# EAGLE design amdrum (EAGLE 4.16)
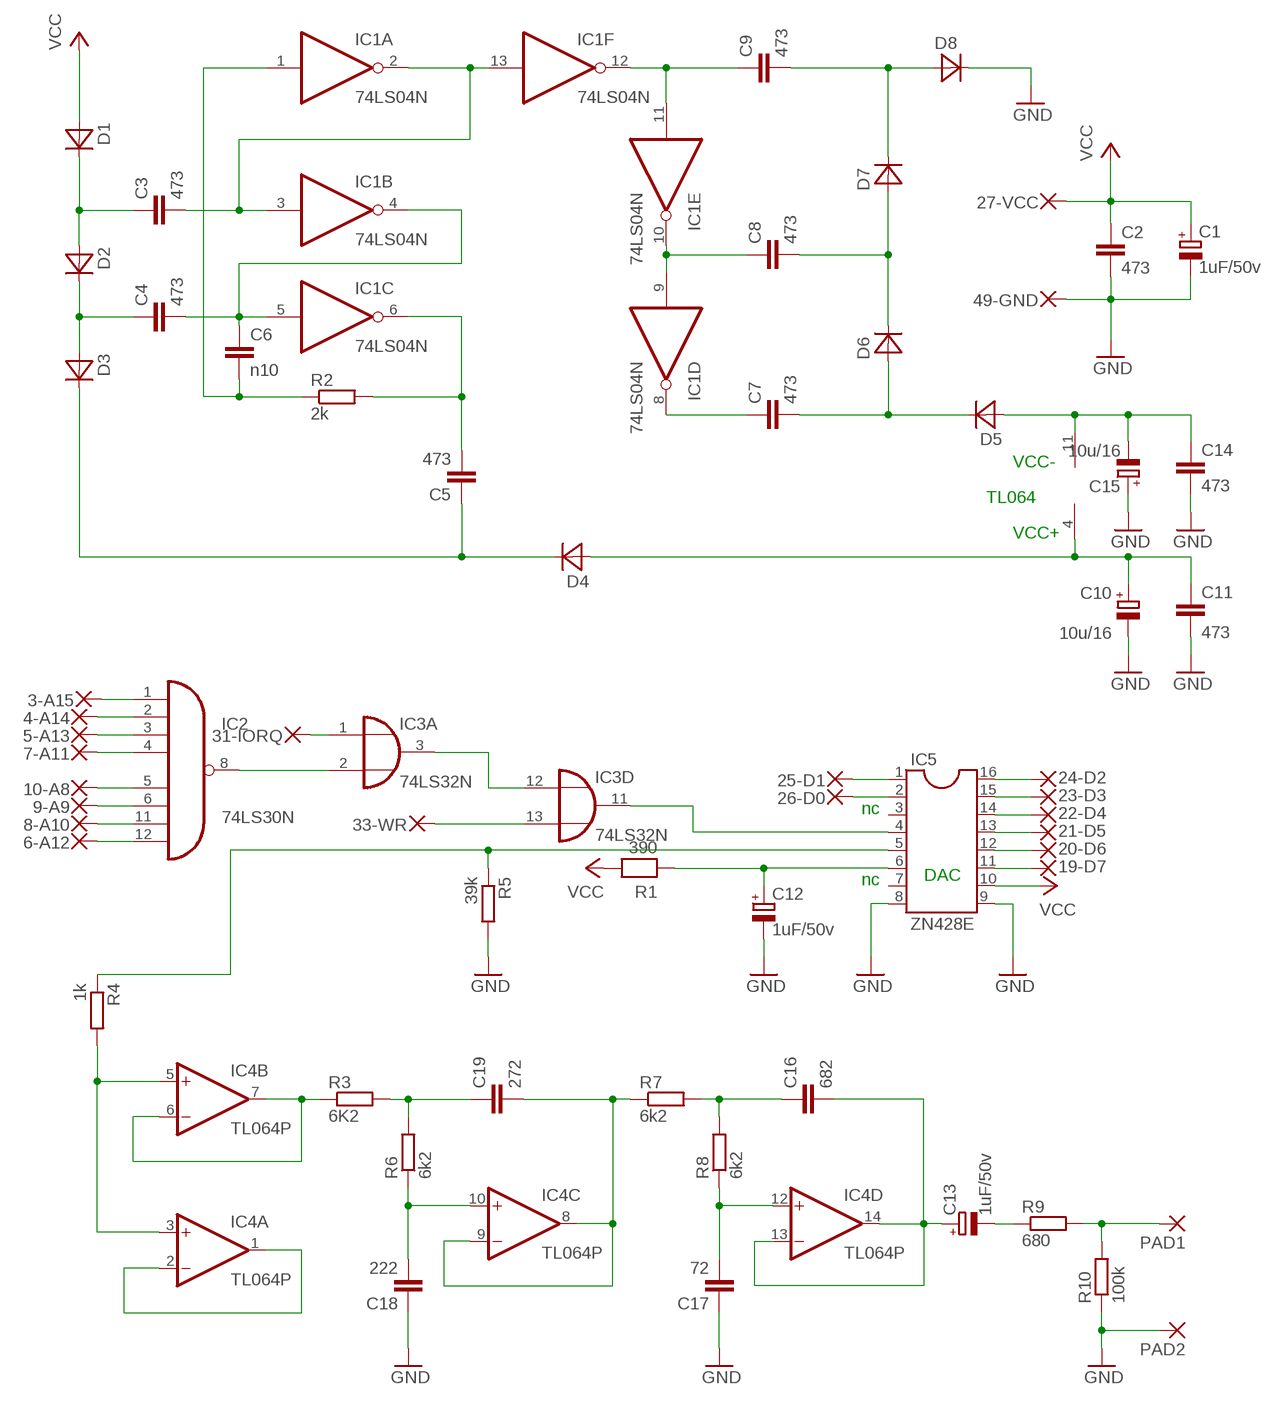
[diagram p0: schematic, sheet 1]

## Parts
3-A15  1,27-REDONDO0.8  [1,27/0,8-REDONDO]
4-A14  1,27-REDONDO0.8  [1,27/0,8-REDONDO]
5-A13  1,27-REDONDO0.8  [1,27/0,8-REDONDO]
6-A12  1,27-REDONDO0.8  [1,27/0,8-REDONDO]
7-A11  1,27-REDONDO0.8  [1,27/0,8-REDONDO]
8-A10  1,27-REDONDO0.8  [1,27/0,8-REDONDO]
9-A9  1,27-REDONDO0.8  [1,27/0,8-REDONDO]
10-A8  1,27-REDONDO0.8  [1,27/0,8-REDONDO]
19-D7  1,27-REDONDO0.8  [1,27/0,8-REDONDO]
20-D6  1,27-REDONDO0.8  [1,27/0,8-REDONDO]
21-D5  1,27-REDONDO0.8  [1,27/0,8-REDONDO]
22-D4  1,27-REDONDO0.8  [1,27/0,8-REDONDO]
23-D3  1,27-REDONDO0.8  [1,27/0,8-REDONDO]
24-D2  1,27-REDONDO0.8  [1,27/0,8-REDONDO]
25-D1  1,27-REDONDO0.8  [1,27/0,8-REDONDO]
26-D0  1,27-REDONDO0.8  [1,27/0,8-REDONDO]
27-VCC  1,27-REDONDO0.8  [1,27/0,8-REDONDO]
31-IORQ  1,27-REDONDO0.8  [1,27/0,8-REDONDO]
33-WR  1,27-REDONDO0.8  [1,27/0,8-REDONDO]
49-GND  1,27-REDONDO0.8  [1,27/0,8-REDONDO]
C1  1uF/50v  CPOL-EUE5-5  [E5-5]
C2  473  C-EU025-025X050  [C025-025X050]
C3  473  C-EU050-024X044  [C050-024X044]
C4  473  C-EU050-024X044  [C050-024X044]
C5  473  C-EU050-024X044  [C050-024X044]
C6  n10  C-EU050-024X044  [C050-024X044]
C7  473  C-EU050-024X044  [C050-024X044]
C8  473  C-EU050-024X044  [C050-024X044]
C9  473  C-EU050-024X044  [C050-024X044]
C10  10u/16  CPOL-EUE5-4  [E5-4]
C11  473  C-EU102-043X133  [C102-043X133]
C12  1uF/50v  CPOL-EUE5-5  [E5-5]
C13  1uF/50v  CPOL-EUE5-5  [E5-5]
C14  473  C-EU025-025X050  [C025-025X050]
C15  10u/16  CPOL-EUE5-4  [E5-4]
C16  682  C-EU025-025X050  [C025-025X050]
C17  72  C-EU050-024X044  [C050-024X044]
C18  222  C-EU050-024X044  [C050-024X044]
C19  272  C-EU050-024X044  [C050-024X044]
D1  DIODE-12,5/2  [D-12,5/2]
D2  DIODE-12,5/2  [D-12,5/2]
D3  DIODE-12,5/2  [D-12,5/2]
D4  DIODE-12,5/2  [D-12,5/2]
D5  DIODE-12,5/2  [D-12,5/2]
D6  DIODE-12,5/2  [D-12,5/2]
D7  DIODE-12,5/2  [D-12,5/2]
D8  DIODE-12,5/2  [D-12,5/2]
IC1  74LS04N  [DIL14]
IC2  74LS30N  [DIL14]
IC3  74LS32N  [DIL14]
IC4  TL064P  [DIL14]
IC5  ZN428E  DIL16  [DIL16]
PAD1  1,6/0,8  [1,6/0,8]
PAD2  1,6/0,8  [1,6/0,8]
R1  390  RESEU-18  [R-18]
R2  2k  R-EU_0207/12  [0207/12]
R3  6K2  R-EU_0207/10  [0207/10]
R4  1k  R-EU_0207/12  [0207/12]
R5  39k  R-EU_0207/12  [0207/12]
R6  6k2  R-EU_0207/12  [0207/12]
R7  6k2  R-EU_0207/12  [0207/12]
R8  6k2  R-EU_0207/10  [0207/10]
R9  680  R-EU_0207/12  [0207/12]
R10  100k  R-EU_0207/12  [0207/12]

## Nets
GND: 49-GND.1(P) C1.- C2.2 C10.- C11.1 C12.- C14.2 C15.+ C17.2 C18.1 D8.P$2(K) IC5.8 IC5.9 PAD2.1(P) R5.2 R10.1
N$25: 3-A15.1(P) IC2.1(I0)
N$26: 4-A14.1(P) IC2.2(I1)
N$27: 6-A12.1(P) IC2.12(I7)
N$28: 5-A13.1(P) IC2.3(I2)
N$30: 7-A11.1(P) IC2.4(I3)
N$31: 8-A10.1(P) IC2.11(I6)
N$32: 10-A8.1(P) IC2.5(I4)
N$33: 9-A9.1(P) IC2.6(I5)
N$34: IC2.8(O) IC3.2(A:I1)
N$35: 31-IORQ.1(P) IC3.1(A:I0)
N$36: 33-WR.1(P) IC3.13(D:I1)
N$37: IC3.3(A:O) IC3.12(D:I0)
N$38: IC3.11(D:O) IC5.4
N$39: 26-D0.1(P) IC5.2
N$40: 25-D1.1(P) IC5.1
N$41: 24-D2.1(P) IC5.16
N$43: 23-D3.1(P) IC5.15
N$47: 22-D4.1(P) IC5.14
N$48: 21-D5.1(P) IC5.13
N$49: 20-D6.1(P) IC5.12
N$54: 19-D7.1(P) IC5.11
N$63: C5.2 IC1.6(C:O) R2.2
N$64: C3.1 D1.P$2(K) D2.P$1(A)
N$65: C3.2 IC1.2(A:O) IC1.3(B:I) IC1.13(F:I)
N$66: C4.1 D2.P$2(K) D3.P$1(A)
N$67: C4.2 C6.1 IC1.4(B:O) IC1.5(C:I)
N$68: C5.1 D3.P$2(K) D4.P$2(K)
N$69: C6.2 IC1.1(A:I) R2.1
N$70: C9.1 IC1.11(E:I) IC1.12(F:O)
N$71: C8.1 IC1.9(D:I) IC1.10(E:O)
N$72: C7.1 IC1.8(D:O)
N$73: C7.2 D5.P$2(K) D6.P$1(A)
N$74: C8.2 D6.P$2(K) D7.P$1(A)
N$75: IC4.6(B:-IN) IC4.7(B:OUT) R3.1
N$76: C9.2 D7.P$2(K) D8.P$1(A)
N$77: C10.+ C11.2 D4.P$1(A) IC4.4(P:V+)
N$78: IC4.1(A:OUT) IC4.2(A:-IN)
N$79: C12.+ IC5.6 R1.1
N$80: IC4.3(A:+IN) IC4.5(B:+IN) R4.2
N$81: C14.1 C15.- D5.P$1(A) IC4.11(P:V-)
N$82: IC5.5 R4.1 R5.1
N$83: C13.- R9.1
N$84: C13.+ C16.2 IC4.13(D:-IN) IC4.14(D:OUT)
N$85: PAD1.1(P) R9.2 R10.2
N$86: C17.1 IC4.12(D:+IN) R8.1
N$87: C16.1 R7.2 R8.2
N$88: C19.1 R3.2 R6.2
N$89: C19.2 IC4.8(C:OUT) IC4.9(C:-IN) R7.1
N$90: C18.2 IC4.10(C:+IN) R6.1
VCC: 27-VCC.1(P) C1.+ C2.1 D1.P$1(A) IC5.10 R1.2
Unconnected: IC3.4(B:I0) IC3.5(B:I1) IC3.6(B:O) IC3.8(C:O) IC3.9(C:I0) IC3.10(C:I1) IC5.3 IC5.7

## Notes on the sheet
- VCC-
- TL064
- VCC+
- nc
- nc | DAC

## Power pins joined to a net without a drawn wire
GND: IC1.7(P:GND) IC2.7(GND) IC3.7(P:GND)
VCC: IC1.14(P:VCC) IC2.14(VCC) IC3.14(P:VCC)

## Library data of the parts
3-A15 4-A14 5-A13 6-A12 7-A11 8-A10 9-A9 10-A8 19-D7 20-D6 21-D5 22-D4 23-D3 24-D2 25-D1 26-D0 27-VCC 31-IORQ 33-WR 49-GND = wirepad2:1,27-REDONDO
C1 C10 C12 C13 C15 = rcl:CPOL-EU: POLARIZED CAPACITOR, European symbol
C2-C9 C11 C14 C16-C19 = rcl:C-EU: CAPACITOR, European symbol
D1-D8 = discrete2:DIODE-12,5/2
IC1 = 74xx-eu:74*04: Hex INVERTER
IC2 = 74xx-eu:74*30: 8-input NAND gate
IC3 = 74xx-eu:74*32: Quad 2-input OR gate
IC4 = linear:TL064: OP AMP
IC5 = ic-package:DIL16: Dual In Line
PAD1 PAD2 = wirepad:1,6/0,8: THROUGH-HOLE PAD
R1 = discrete2:RESEU-18
R2-R10 = rcl:R-EU_: RESISTOR, European symbol

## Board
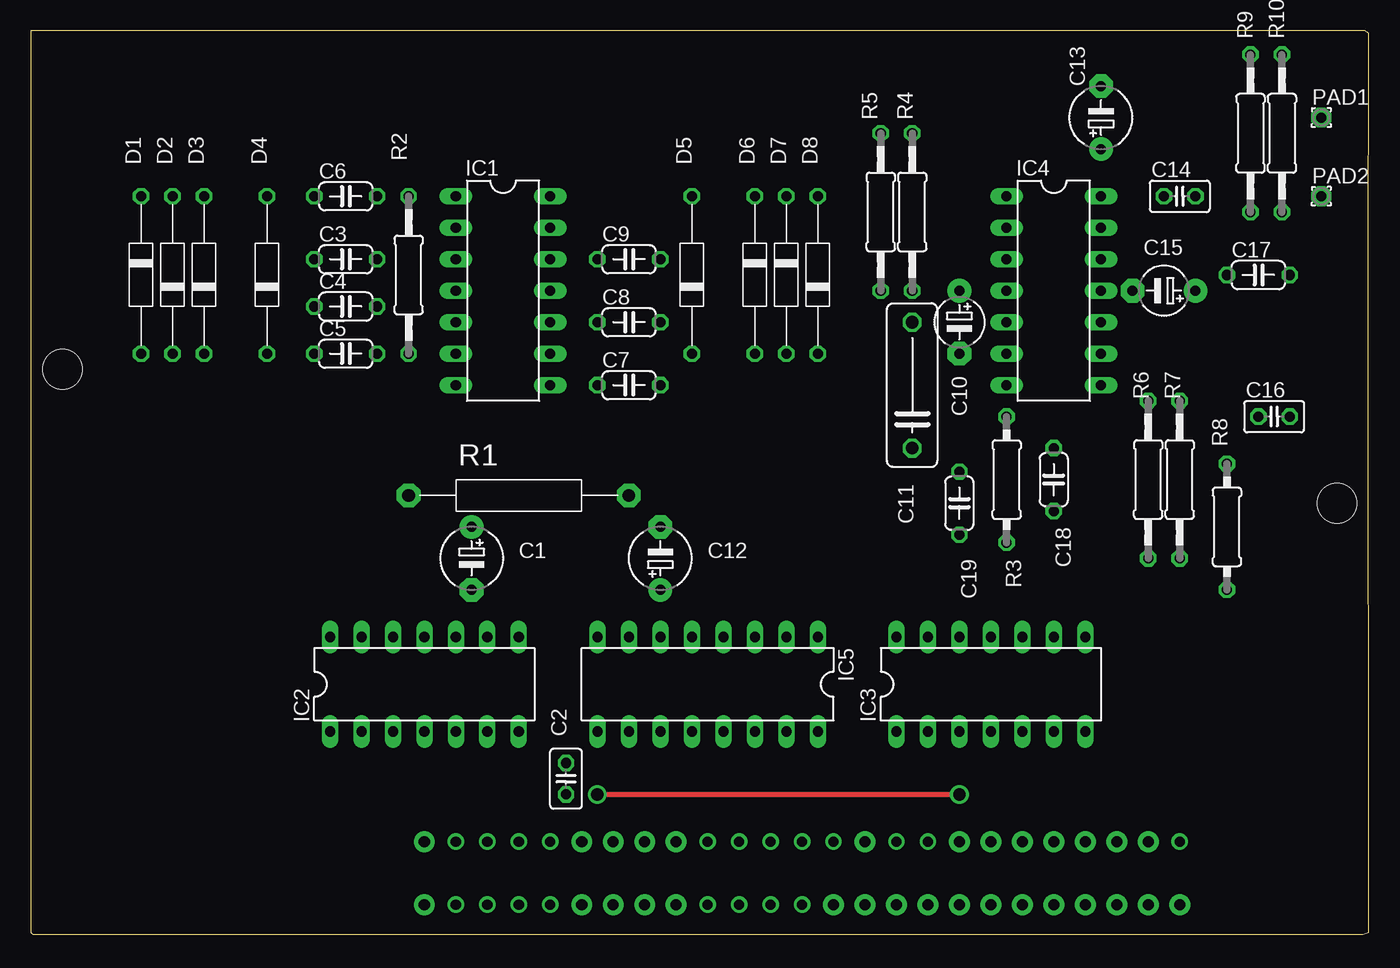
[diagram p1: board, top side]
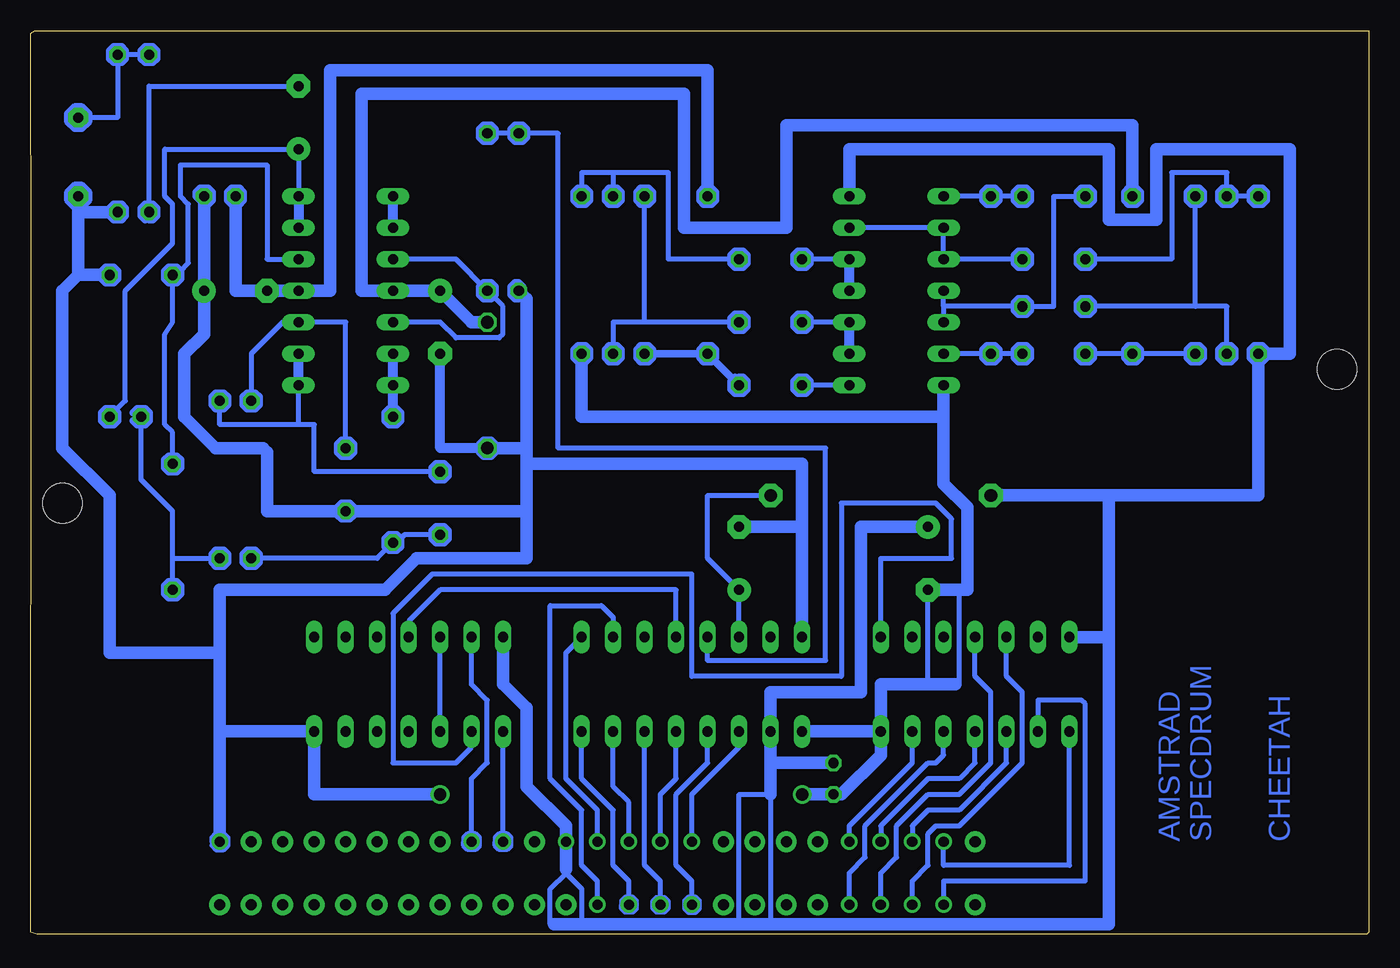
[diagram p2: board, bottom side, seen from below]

Size 107.95 x 72.86 mm. Coordinates in mm from the lower left corner, seen from the top.
Outline: 107.48,0 107.95,0.15 107.94,53.01 107.95,72.69 107.63,72.86 0,72.86 0,0.15 0.15,0 107.48,0
Copper layers (1*16): Top 0.035mm / dielectric 1.5mm / Bottom 0.035mm
Design rules "default": minimum track width 10mil, minimum drill 24mil, track to track 8mil, track to pad 8mil, pad to pad 8mil, via to via 8mil, smd to smd 8mil, copper to edge 40mil, drill to drill 8mil, minimum pad ring 10mil, minimum via ring 8mil, stop-mask expansion 4mil, vias tented up to drill 0mil, thermal gap 10mil
Holes 3.2 mm at 2.54,45.55 105.41,34.76

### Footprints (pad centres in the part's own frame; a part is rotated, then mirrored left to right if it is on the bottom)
1,27/0,8-REDONDO = drill 0.813 pad 1.27 round: 1 0,0
E5-5 = drill 0.813 pad 1.905 round: + -2.54,0 | drill 0.813 pad 1.905 octagon: - 2.54,0
C025-025X050 = drill 0.813 octagon: 1 -1.27,0; 2 1.27,0
C050-024X044 = drill 0.813 octagon: 1 -2.54,0; 2 2.54,0
E5-4 = drill 0.813 pad 1.905 round: + -2.54,0 | drill 0.813 pad 1.905 octagon: - 2.54,0
C102-043X133 = drill 1.016 octagon: 1 -5.08,0; 2 5.08,0
D-12,5/2 = drill 0.813 octagon: P$1 -6.35,0; P$2 6.35,0
DIL14 = drill 0.813 long: 1 -7.62,-3.81; 2 -5.08,-3.81; 3 -2.54,-3.81; 4 0,-3.81; 5 2.54,-3.81; 6 5.08,-3.81; 7 7.62,-3.81; 8 7.62,3.81; 9 5.08,3.81; 10 2.54,3.81; 11 0,3.81; 12 -2.54,3.81; 13 -5.08,3.81; 14 -7.62,3.81
DIL16 = drill 0.813 long: 1 -8.89,-3.81; 2 -6.35,-3.81; 3 -3.81,-3.81; 4 -1.27,-3.81; 5 1.27,-3.81; 6 3.81,-3.81; 7 6.35,-3.81; 8 8.89,-3.81; 9 8.89,3.81; 10 6.35,3.81; 11 3.81,3.81; 12 1.27,3.81; 13 -1.27,3.81; 14 -3.81,3.81; 15 -6.35,3.81; 16 -8.89,3.81
1,6/0,8 = drill 0.813 pad 1.6 octagon: 1 0,0
R-18 = drill 1.016 pad 1.905 octagon: 1 -8.89,0; 2 8.89,0
0207/12 = drill 0.813 octagon: 1 -6.35,0; 2 6.35,0
0207/10 = drill 0.813 octagon: 1 -5.08,0; 2 5.08,0

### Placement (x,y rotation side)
3-A15  34.29,7.46 0 top
4-A14  34.29,2.38 180 top
5-A13  36.83,7.46 0 top
6-A12  36.83,2.38 180 top
7-A11  39.37,7.46 0 top
8-A10  39.37,2.38 180 top
9-A9  41.91,7.46 0 top
10-A8  41.91,2.38 180 top
19-D7  54.61,7.46 0 top
20-D6  54.61,2.38 180 top
21-D5  57.15,7.46 0 top
22-D4  57.15,2.38 180 top
23-D3  59.69,7.46 0 top
24-D2  59.69,2.38 180 top
25-D1  62.23,7.46 0 top
26-D0  62.23,2.38 180 top
27-VCC  64.77,7.46 0 top
31-IORQ  69.85,7.46 0 top
33-WR  72.39,7.46 0 top
49-GND  92.71,7.46 0 top
C1  35.56,30.32 270 top
C2  43.18,12.54 270 top
C3  25.4,54.45 0 top
C4  25.4,50.63 0 top
C5  25.4,46.83 0 top
C6  25.4,59.52 0 top
C7  48.26,44.29 0 top
C8  48.26,49.37 0 top
C9  48.26,54.45 0 top
C10  74.93,49.37 270 top
C11  71.12,44.29 90 top
C12  50.8,30.32 90 top
C13  86.36,65.88 90 top
C14  92.71,59.52 0 top
C15  91.44,51.91 180 top
C16  100.33,41.74 0 top
C17  99.06,53.18 0 top
C18  82.55,36.66 90 top
C19  74.93,34.76 90 top
D1  8.89,53.18 90 top
D2  11.43,53.18 270 top
D3  13.97,53.18 270 top
D4  19.05,53.18 270 top
D5  53.34,53.18 270 top
D6  58.42,53.18 90 top
D7  60.96,53.18 90 top
D8  63.5,53.18 270 top
IC1  38.1,51.91 270 top
IC2  31.75,20.16 0 top
IC3  77.47,20.16 0 top
IC4  82.55,51.91 270 top
IC5  54.61,20.16 180 top
PAD1  104.14,65.88 0 top
PAD2  104.14,59.52 0 top
R1  39.37,35.4 180 top
R2  30.48,53.18 270 top
R3  78.74,36.66 270 top
R4  71.12,58.26 270 top
R5  68.58,58.26 270 top
R6  90.17,36.66 270 top
R7  92.71,36.66 270 top
R8  96.52,32.86 270 top
R9  98.42,64.6 90 top
R10  100.97,64.6 90 top

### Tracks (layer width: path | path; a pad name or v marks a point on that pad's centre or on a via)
GND  (via drill 1, 1 pad 1.42)
  Top 0.406: v45.72,11.27 v74.93,11.27
  Bottom 0.406: 33.34,20.16 33.02,20.16 33.02,27.78 | 35.56,20.16 C1.- | 49-GND.1 93.34,7.46 | 93.34,7.46 93.34,7.14 93.03,6.82 92.39,6.82 92.08,7.14 92.08,7.77 92.39,8.09 93.03,8.09 93.34,7.77 93.34,7.46 | PAD2.1 104.14,60.48 | 104.14,60.48 104.46,60.48 105.09,59.84 105.09,59.21 104.46,58.57 103.82,58.57 103.19,59.21 103.19,59.84 103.82,60.48 104.14,60.48
  Bottom 0.61: C18.1 82.55,34.76 | 82.55,34.76 82.87,34.76 83.19,34.44 83.19,33.81 82.87,33.49 82.23,33.49 81.92,33.81 81.92,34.44 82.23,34.76 82.55,34.76 | C17.2 101.6,53.81 | 101.6,53.81 101.28,53.81 100.97,53.49 100.97,52.86 101.28,52.54 101.92,52.54 102.23,52.86 102.23,53.49 101.92,53.81 101.6,53.81 | R10.1 100.97,58.89 | 100.97,58.89 100.65,58.89 100.33,58.57 100.33,57.94 100.65,57.62 101.28,57.62 101.6,57.94 101.6,58.57 101.28,58.89 100.97,58.89 | D8.P$2 63.5,47.46 | 63.5,47.46 63.82,47.46 64.14,47.14 64.14,46.51 63.82,46.19 63.18,46.19 62.87,46.51 62.87,47.14 63.18,47.46 63.5,47.46 | 71.12,39.84 C11.1 71.12,38.57 | R5.2 69.22,52.22 | 69.22,52.22 68.9,52.54 68.58,52.54 68.26,52.22 68.26,51.59 68.58,51.27 68.9,51.27 69.22,51.59 69.22,52.22 | C14.2 94.61,59.84 | 94.61,59.84 94.3,60.16 93.66,60.16 93.34,59.84 93.34,59.21 93.66,58.89 93.98,58.89 94.61,59.52 94.61,59.84 | 71.12,38.57 71.44,38.57 71.75,38.89 71.75,39.52 71.44,39.84 70.8,39.84 70.48,39.52 70.48,38.89 70.8,38.57 71.12,38.57
  Bottom 0.813: C10.- 74.93,39.2 C11.1
  Bottom 1.016: 92.71,16.35 49-GND.1 | 92.71,16.35 IC3.7 85.09,11.27 v74.93,11.27 | v45.72,11.27 C2.2 42.55,11.27 39.37,14.44 IC2.7 | IC2.7 IC5.9 | IC2.7 39.37,20.16 35.56,20.16 33.34,20.16 | 34.29,41.74 34.29,36.35 32.38,34.44 32.38,27.78 C1.- | 34.29,41.74 IC1.7 | D8.P$2 63.5,41.74 34.29,41.74 | 92.71,16.35 92.71,22.7 | 92.71,22.7 92.71,27.78 79.38,27.78 76.83,30.32 67.94,30.32 67.94,34.12 | 67.94,34.12 67.94,37.94 | 67.94,37.94 67.94,39.2 | 67.94,39.2 C11.1 | 45.72,32.86 45.72,37.94 67.94,37.94 | 45.72,32.86 IC5.8 | 45.72,32.86 C12.- | R5.2 68.26,51.59 67.94,51.27 67.94,39.2 | 104.14,58.26 R10.1 | 104.14,58.26 PAD2.1 | 104.14,53.18 C17.2 | 104.14,53.18 104.14,58.26 | 104.14,53.18 105.41,51.91 105.41,39.2 101.6,35.4 101.6,22.7 92.71,22.7 | C14.2 93.98,58.89 C15.+ 93.98,48.41 95.57,46.83 95.57,41.74 93.03,39.2 89.22,39.2 88.9,38.89 88.9,34.12 C18.1 67.94,34.12
N$2  (via drill 0.9 pad 1.68)
  other vias: 31.75,7.46
N$4  (via drill 0.9 pad 1.68)
  other vias: 72.39,2.38
N$5  (via drill 0.9 pad 1.68)
  other vias: 85.09,7.46
N$8  (via drill 0.9 pad 1.68)
  other vias: 74.93,7.46
N$9  (via drill 0.9 pad 1.68)
  other vias: 77.47,2.38
N$10  (via drill 0.9 pad 1.68)
  other vias: 77.47,7.46
N$11  (via drill 0.9 pad 1.68)
  other vias: 80.01,7.46
N$12  (via drill 0.9 pad 1.68)
  other vias: 82.55,2.38
N$13  (via drill 0.9 pad 1.68)
  other vias: 85.09,2.38
N$14  (via drill 0.9 pad 1.68)
  other vias: 87.63,2.38
N$22  (via drill 0.9 pad 1.68)
  other vias: 90.17,2.38
N$23  (via drill 0.9 pad 1.68)
  other vias: 90.17,7.46
N$24  (via drill 0.9 pad 1.68)
  other vias: 31.75,2.38
N$25
  Bottom 0.406: 3-A15.1 34.29,5.55 24.13,5.55 IC2.1
N$26
  Bottom 0.406: 4-A14.1 34.29,4.28 22.86,4.28 22.86,18.57 23.18,18.89 26.67,18.89 IC2.2
N$27
  Bottom 0.406: IC2.12 29.21,20.79 27.94,19.52 27.94,13.81 33.02,8.73 34.92,8.73 35.56,8.09 35.56,5.55 36.83,4.28 6-A12.1
N$28
  Bottom 0.406: 5-A13.1 36.83,8.73 35.56,10 33.02,10 29.21,13.81 IC2.3
N$29  (via drill 0.9 pad 1.68)
  other vias: 92.71,2.38
N$30
  Bottom 0.406: 7-A11.1 39.37,8.73 35.56,12.54 33.02,12.54 31.75,13.81 IC2.4
N$31
  Bottom 0.406: 8-A10.1 39.37,4.92 38.1,6.18 38.1,8.73 35.56,11.27 33.02,11.27 30.48,13.81 30.48,19.52 31.75,20.79 IC2.11
N$32
  Bottom 0.406: IC2.5 34.29,14.44 34.92,13.81 35.56,13.81 40.64,8.73 40.64,6.18 41.91,4.92 10-A8.1
N$33
  Bottom 0.406: IC2.6 36.83,13.81 41.91,8.73 9-A9.1
N$34
  Bottom 0.406: IC2.8 39.37,30.32 33.66,30.32 33.66,33.49 34.92,34.76 42.55,34.76 42.55,20.79 54.61,20.79 54.61,29.05 75.56,29.05 78.74,25.87 78.74,13.81 73.66,13.81 72.39,15.08 IC3.2
N$35
  Bottom 0.406: IC3.1 31-IORQ.1 70.48,7.46 | 70.48,7.46 70.48,7.14 70.17,6.82 69.53,6.82 69.22,7.14 69.22,7.77 69.53,8.09 70.17,8.09 70.48,7.77 70.48,7.46
N$36
  Bottom 0.406: IC3.13 72.39,20.16 71.12,18.89 71.12,13.81 72.39,12.54 33-WR.1 73.03,7.46 | 73.03,7.46 73.03,7.14 72.71,6.82 72.07,6.82 71.75,7.14 71.75,7.77 72.07,8.09 72.71,8.09 73.03,7.77 73.03,7.46
N$37
  Bottom 0.406: IC3.3 IC3.12
N$38
  Bottom 0.406: IC3.11 77.47,25.23 74.93,27.78 55.88,27.78 IC5.4
N$39
  Bottom 0.406: 26-D0.1 62.23,4.28 63.5,5.55 63.5,10 66.04,12.54 66.04,26.51 61.91,26.51 60.96,25.55 IC5.2
N$40
  Bottom 0.406: 25-D1.1 62.23,10 64.77,12.54 64.77,22.7 IC5.1
N$41
  Bottom 0.305: 60.33,2.38 24-D2.1 | 60.33,2.38 60.33,2.06 60.01,1.74 59.37,1.74 59.05,2.06 59.05,2.69 59.37,3.01 60.01,3.01 60.33,2.69 60.33,2.38
  Bottom 0.406: 24-D2.1 59.69,4.28 60.96,5.55 60.96,10 63.5,12.54 IC5.16
N$42  (via drill 0.9 pad 1.68)
  other vias: 80.01,2.38
N$43
  Bottom 0.406: 23-D3.1 59.69,10.63 60.96,11.9 IC5.15
N$44  (via drill 0.9 pad 1.68)
  other vias: 74.93,2.38
N$45  (via drill 0.9 pad 1.68)
  other vias: 87.63,7.46
N$46  (via drill 0.9 pad 1.68)
  other vias: 82.55,7.46
N$47
  Bottom 0.305: 22-D4.1 57.78,2.38 | 57.78,2.38 57.78,2.69 57.47,3.01 56.83,3.01 56.52,2.69 56.52,2.06 56.83,1.74 57.47,1.74 57.78,2.06 57.78,2.38
  Bottom 0.406: IC5.14 58.42,5.55 57.15,4.28 22-D4.1
N$48
  Bottom 0.406: 21-D5.1 57.15,11.27 55.88,12.54 IC5.13
N$49
  Bottom 0.305: 20-D6.1 55.24,2.38 | 55.24,2.38 55.24,2.06 54.93,1.74 54.29,1.74 53.98,2.06 53.98,2.69 54.29,3.01 54.93,3.01 55.24,2.69 55.24,2.38
  Bottom 0.406: IC5.12 53.34,13.81 55.88,11.27 55.88,5.55 54.61,4.28 20-D6.1
N$50  (via drill 0.9 pad 1.68)
  other vias: 67.31,7.46
N$51  (via drill 0.9 pad 1.68)
  other vias: 67.31,2.38
N$52  (via drill 0.9 pad 1.68)
  other vias: 69.85,2.38
N$53  (via drill 0.9 pad 1.68)
  other vias: 64.77,2.38
N$54
  Bottom 0.406: IC5.11 50.8,15.08 54.61,11.27 19-D7.1
N$55  (via drill 0.9 pad 1.68)
  other vias: 52.07,7.46
N$56  (via drill 0.9 pad 1.68)
  other vias: 52.07,2.38
N$57  (via drill 0.9 pad 1.68)
  other vias: 49.53,7.46
N$58  (via drill 0.9 pad 1.68)
  other vias: 49.53,2.38
N$59  (via drill 0.9 pad 1.68)
  other vias: 46.99,7.46
N$60  (via drill 0.9 pad 1.68)
  other vias: 44.45,7.46
N$61  (via drill 0.9 pad 1.68)
  other vias: 44.45,2.38
N$62  (via drill 0.9 pad 1.68)
  other vias: 46.99,2.38
N$63
  Bottom 0.406: R2.2 C5.2 R2.2 | R2.2 IC1.6
  Bottom 0.61: R2.2 30.48,46.19 | 30.48,46.19 30.16,46.19 29.84,46.51 29.84,47.14 30.16,47.46 30.8,47.46 31.11,47.14 31.11,46.51 30.8,46.19 30.48,46.19 | 27.94,47.46 C5.2 | 27.94,47.46 28.26,47.46 28.57,47.14 28.57,46.51 28.26,46.19 27.62,46.19 27.3,46.51 27.3,47.14 27.62,47.46 27.94,47.46
N$64
  Bottom 0.406: C3.1 15.88,54.45 15.88,61.43 11.43,61.43 D2.P$1 D1.P$2
  Bottom 0.61: 22.86,55.08 23.18,55.08 23.5,54.76 23.5,54.13 23.18,53.81 22.54,53.81 22.23,54.13 22.23,54.76 22.54,55.08 22.86,55.08 | C3.1 22.86,55.08 | D2.P$1 11.43,58.89 | 11.43,58.89 11.75,58.89 12.06,59.21 12.06,59.84 11.75,60.16 11.11,60.16 10.79,59.84 10.79,59.21 11.11,58.89 11.43,58.89 | D1.P$2 8.89,60.16 | 8.89,60.16 9.21,60.16 9.53,59.84 9.53,59.21 9.21,58.89 8.57,58.89 8.26,59.21 8.26,59.84 8.57,60.16 8.89,60.16
N$65
  Bottom 0.406: C3.2 IC1.3 IC1.2 IC1.13
  Bottom 0.61: 27.94,55.08 C3.2 | 27.94,55.08 28.26,55.08 28.57,54.76 28.57,54.13 28.26,53.81 27.62,53.81 27.3,54.13 27.3,54.76 27.62,55.08 27.94,55.08
N$66
  Bottom 0.406: 13.97,50.63 C4.1 | 13.97,50.63 D3.P$1 | D2.P$2 11.43,50.63 13.97,50.63
  Bottom 0.61: C4.1 22.86,51.27 | 22.86,51.27 23.18,51.27 23.5,50.95 23.5,50.32 23.18,50 22.54,50 22.23,50.32 22.23,50.95 22.54,51.27 22.86,51.27 | D3.P$1 13.97,60.16 | 13.97,60.16 14.29,60.16 14.61,59.84 14.61,59.21 14.29,58.89 13.65,58.89 13.34,59.21 13.34,59.84 13.65,60.16 13.97,60.16 | D2.P$2 11.43,46.19 | 11.43,46.19 11.11,46.19 10.79,46.51 10.79,47.14 11.11,47.46 11.75,47.46 12.06,47.14 12.06,46.51 11.75,46.19 11.43,46.19
N$67
  Bottom 0.406: 34.29,50.63 C4.2 25.4,50.63 25.4,59.52 C6.1 | 34.29,50.63 IC1.5 | 34.29,50.63 IC1.4
  Bottom 0.61: 27.94,51.27 C4.2 | 27.94,51.27 28.26,51.27 28.57,50.95 28.57,50.32 28.26,50 27.62,50 27.3,50.32 27.3,50.95 27.62,51.27 27.94,51.27 | C6.1 22.86,60.16 | 22.86,60.16 23.18,60.16 23.5,59.84 23.5,59.21 23.18,58.89 22.54,58.89 22.23,59.21 22.23,59.84 22.54,60.16 22.86,60.16
N$68
  Bottom 0.406: D4.P$2 19.37,46.83 | D3.P$2 D4.P$2 | D4.P$2 C5.1
  Bottom 0.61: C5.1 22.86,47.46 | 22.86,47.46 23.18,47.46 23.5,47.14 23.5,46.51 23.18,46.19 22.54,46.19 22.23,46.51 22.23,47.14 22.54,47.46 22.86,47.46 | 19.05,47.46 19.37,47.46 19.68,47.14 19.68,46.51 19.37,46.19 18.73,46.19 18.41,46.51 18.41,47.14 18.73,47.46 19.05,47.46 | D4.P$2 19.05,47.46 | D3.P$2 13.97,47.46 | 13.97,47.46 13.65,47.46 13.34,47.14 13.34,46.51 13.65,46.19 14.29,46.19 14.61,46.51 14.61,47.14 14.29,47.46 13.97,47.46
N$69
  Bottom 0.406: C6.2 R2.1 IC1.1
  Bottom 0.61: R2.1 30.48,60.16 | 30.48,60.16 30.8,60.16 31.11,59.84 31.11,59.21 30.8,58.89 30.16,58.89 29.84,59.21 29.84,59.84 30.16,60.16 30.48,60.16 | C6.2 27.94,60.16 28.26,60.16 | 28.26,60.16 28.57,59.84 28.57,59.21 28.26,58.89 27.62,58.89 27.3,59.21 27.3,59.84 27.62,60.16 28.26,60.16
N$70
  Bottom 0.406: IC1.12 C9.1
  Bottom 0.61: C9.1 45.72,55.08 | 45.72,55.08 46.04,55.08 46.35,54.76 46.35,54.13 46.04,53.81 45.4,53.81 45.09,54.13 45.09,54.76 45.4,55.08 45.72,55.08
  Bottom 0.813: IC1.11 IC1.12
N$71
  Bottom 0.406: IC1.10 C8.1
  Bottom 0.61: C8.1 45.72,50 | 45.72,50 46.04,50 46.35,49.68 46.35,49.05 46.04,48.73 45.4,48.73 45.09,49.05 45.09,49.68 45.4,50 45.72,50
  Bottom 0.813: IC1.9 IC1.10
N$72
  Bottom 0.406: IC1.8 C7.1
  Bottom 0.61: C7.1 45.72,44.92 | 45.72,44.92 46.04,44.92 46.35,44.6 46.35,43.97 46.04,43.65 45.4,43.65 45.09,43.97 45.09,44.6 45.4,44.92 45.72,44.92
N$73
  Bottom 0.61: D5.P$2 C7.2 50.8,44.92 50.48,44.92 50.16,44.6 50.16,43.97 50.48,43.65 51.12,43.65 51.44,43.97 51.44,44.6 51.12,44.92 | D5.P$2 D6.P$1 58.42,47.46 | 58.42,47.46 58.74,47.46 59.05,47.14 59.05,46.51 58.74,46.19 58.1,46.19 57.78,46.51 57.78,47.14 58.1,47.46 58.42,47.46 | D5.P$2 53.34,47.46 | 53.34,47.46 53.66,47.46 53.98,47.14 53.98,46.51 53.66,46.19 53.02,46.19 52.7,46.51 52.7,47.14 53.02,47.46 53.34,47.46
N$74
  Bottom 0.406: C8.2 58.42,49.37 | 58.42,49.37 60.96,49.37 D7.P$1 | 58.42,49.37 D6.P$2
  Bottom 0.61: D7.P$1 60.96,46.19 | 60.96,46.19 61.28,46.19 61.59,46.51 61.59,47.14 61.28,47.46 60.64,47.46 60.33,47.14 60.33,46.51 60.64,46.19 60.96,46.19 | 50.8,50 C8.2 | 50.8,50 51.12,50 51.44,49.68 51.44,49.05 51.12,48.73 50.48,48.73 50.16,49.05 50.16,49.68 50.48,50 50.8,50 | D6.P$2 58.42,60.16 | 58.42,60.16 58.74,60.16 59.05,59.84 59.05,59.21 58.74,58.89 58.1,58.89 57.78,59.21 57.78,59.84 58.1,60.16 58.42,60.16
N$75
  Bottom 0.61: 79.38,41.74 R3.1 | 79.38,41.74 79.38,41.43 79.06,41.11 78.42,41.11 78.11,41.43 78.11,42.06 78.42,42.38 79.06,42.38 79.38,42.06 79.38,41.74
  Bottom 0.813: IC4.6 IC4.7 R3.1
N$76
  Bottom 0.406: C9.2 56.52,54.45 56.52,61.43 60.96,61.43 | 60.96,61.43 63.5,61.43 D8.P$1 | 60.96,61.43 D7.P$2
  Bottom 0.61: D8.P$1 64.14,59.52 | 64.14,59.52 64.14,59.21 63.82,58.89 63.18,58.89 62.87,59.21 62.87,59.84 63.18,60.16 63.82,60.16 64.14,59.84 64.14,59.52 | D7.P$2 61.59,59.52 | 61.59,59.52 61.59,59.21 61.28,58.89 60.64,58.89 60.33,59.21 60.33,59.84 60.64,60.16 61.28,60.16 61.59,59.84 61.59,59.52 | 50.8,55.08 C9.2 | 50.8,55.08 51.12,55.08 51.44,54.76 51.44,54.13 51.12,53.81 50.48,53.81 50.16,54.13 50.16,54.76 50.48,55.08 50.8,55.08
N$77
  Bottom 0.61: D4.P$1 19.05,58.89 | 19.05,58.89 18.73,58.89 18.41,59.21 18.41,59.84 18.73,60.16 19.37,60.16 19.68,59.84 19.68,59.21 19.37,58.89 19.05,58.89
  Bottom 1.016: D4.P$1 19.05,65.24 46.99,65.24 46.99,56.98 55.24,56.98 55.24,67.78 81.28,67.78 81.28,51.91 IC4.4 C10.+ 72.39,49.37 C11.2
N$78
  Bottom 0.813: IC4.2 IC4.1
N$79
  Bottom 0.406: IC5.6 50.8,27.46 51.12,27.78 C12.+ 53.34,30.32 53.34,35.4 R1.1
N$80
  Bottom 0.406: IC4.3 73.66,54.45 R4.2 69.85,50.63 69.85,48.41 70.17,48.09 73.66,48.09 74.93,49.37 IC4.5
  Bottom 0.61: R4.2 71.12,52.54 | 71.12,52.54 71.44,52.54 71.75,52.22 71.75,51.59 71.44,51.27 70.8,51.27 70.48,51.59 70.48,52.22 70.8,52.54 71.12,52.54
N$81
  Bottom 0.61: 53.98,59.52 D5.P$1 | 53.98,59.52 53.98,59.21 53.66,58.89 53.02,58.89 52.7,59.21 52.7,59.84 53.02,60.16 53.66,60.16 53.98,59.84 53.98,59.52 | 90.81,59.52 90.81,59.84 91.12,60.16 91.76,60.16 92.08,59.84 92.08,59.21 91.76,58.89 91.12,58.89 90.81,59.21 90.81,59.52 | C14.1 90.81,59.52
  Bottom 0.813: 91.44,59.21 C14.1
  Bottom 1.016: 91.44,59.21 91.44,51.91 C15.- IC4.11 83.82,51.91 83.82,69.68 53.34,69.68 D5.P$1
N$82
  Bottom 0.406: R4.1 68.9,64.6 68.58,64.92 R5.1 65.41,64.6 65.41,39.2 43.81,39.2 43.81,22.06 53.34,22.06 IC5.5
  Bottom 0.61: R4.1 71.12,65.24 | 71.12,65.24 71.44,65.24 71.75,64.92 71.75,64.29 71.44,63.97 70.8,63.97 70.48,64.29 70.48,64.92 70.8,65.24 71.12,65.24 | R5.1 68.58,65.24 | 68.58,65.24 68.9,65.24 69.22,64.92 69.22,64.29 68.9,63.97 68.26,63.97 67.94,64.29 67.94,64.92 68.26,65.24 68.58,65.24
N$83
  Bottom 0.406: C13.- 98.42,68.41 R9.1
  Bottom 0.61: R9.1 98.42,57.62 98.11,57.62 97.79,57.94 97.79,58.57 98.11,58.89 98.74,58.89 99.06,58.57 99.06,57.94 98.74,57.62
N$84
  Bottom 0.406: IC4.14 C13.+ 97.16,63.34 97.16,59.52 96.52,58.89 96.52,55.72 100.33,51.91 100.33,43.02 C16.2
  Bottom 0.61: C16.2 101.6,41.11 | 101.6,41.11 101.92,41.11 102.23,41.43 102.23,42.06 101.92,42.38 101.28,42.38 100.97,42.06 100.97,41.43 101.28,41.11 101.6,41.11
  Bottom 0.813: IC4.14 IC4.13
N$85
  Bottom 0.406: R9.2 R10.2 100.97,65.88 PAD1.1 104.14,66.83 | 104.14,66.83 104.46,66.83 105.09,66.19 105.09,65.56 104.46,64.92 103.82,64.92 103.19,65.56 103.19,66.19 103.82,66.83 104.14,66.83
  Bottom 0.61: R10.2 100.97,71.59 | 100.97,71.59 101.28,71.59 101.6,71.27 101.6,70.64 101.28,70.32 100.65,70.32 100.33,70.64 100.33,71.27 100.65,71.59 100.97,71.59 | 98.42,71.59 R9.2 | 98.42,71.59 98.74,71.59 99.06,71.27 99.06,70.64 98.74,70.32 98.11,70.32 97.79,70.64 97.79,71.27 98.11,71.59 98.42,71.59
N$86
  Bottom 0.406: IC4.12 88.9,54.45 88.9,62.06 95.89,62.06 95.89,59.52 95.25,58.89 95.25,54.13 95.89,53.49 96.52,52.86 C17.1 96.52,49.37 97.16,48.41 97.16,41.11 96.52,40.48 96.52,38.57 R8.1
  Bottom 0.61: C17.1 97.16,53.18 | 97.16,53.18 97.16,52.86 96.84,52.54 96.2,52.54 95.89,52.86 95.89,53.49 96.2,53.81 96.84,53.81 97.16,53.49 97.16,53.18 | 96.52,38.57 96.84,38.57 97.16,38.25 97.16,37.62 96.84,37.3 96.2,37.3 95.89,37.62 95.89,38.25 96.2,38.57 96.52,38.57
N$87
  Bottom 0.406: 96.52,30 96.52,30.32 93.34,30.32 R7.2 | 96.52,30 96.52,28.41 R8.2 | C16.1 99.06,36.66 96.52,34.12 96.52,30
  Bottom 0.61: C16.1 99.69,42.06 99.38,42.38 98.74,42.38 98.42,42.06 98.42,41.43 98.74,41.11 99.38,41.11 99.69,41.43 | 96.52,28.41 96.84,28.41 97.16,28.09 97.16,27.46 96.84,27.14 96.2,27.14 95.89,27.46 95.89,28.09 96.2,28.41 96.52,28.41 | 93.34,30.32 93.34,30 93.03,29.68 92.39,29.68 92.08,30 92.08,30.63 92.39,30.95 93.03,30.95 93.34,30.63 93.34,30.32
N$88
  Bottom 0.406: R6.2 89.53,30.32 80.01,30.32 R3.2 78.42,31.59 78.11,31.9 77.79,32.22 C19.1
  Bottom 0.61: 78.74,32.22 R3.2 | 78.74,32.22 79.06,32.22 79.38,31.9 79.38,31.27 79.06,30.95 78.42,30.95 78.11,31.27 78.11,31.9 78.42,32.22 78.74,32.22 | C19.1 74.93,31.59 | 74.93,31.59 74.61,31.59 74.3,31.9 74.3,32.54 74.61,32.86 75.25,32.86 75.56,32.54 75.56,31.9 75.25,31.59 74.93,31.59 | 89.53,30.32 89.53,30 89.85,29.68 90.49,29.68 90.81,30 90.81,30.63 90.49,30.95 89.85,30.95 89.53,30.63 89.53,30.32
N$89
  Bottom 0.406: C19.2 85.09,37.3 85.09,41.11 86.36,41.11 | 86.36,41.11 IC4.8 | 86.36,41.11 92.71,41.11 92.71,42.38 R7.1
  Bottom 0.61: C19.2 74.93,37.94 | 74.93,37.94 75.25,37.94 75.56,37.62 75.56,36.98 75.25,36.66 74.61,36.66 74.3,36.98 74.3,37.62 74.61,37.94 74.93,37.94 | 92.71,42.38 93.03,42.38 93.34,42.7 93.34,43.33 93.03,43.65 92.39,43.65 92.08,43.33 92.08,42.7 92.39,42.38 92.71,42.38
  Bottom 0.813: IC4.8 IC4.9
N$90
  Bottom 0.406: R6.1 90.17,43.65 90.17,46.83 87.63,49.37 IC4.10 82.55,49.37 82.55,39.84 C18.2
  Bottom 0.61: 90.17,43.65 90.49,43.65 90.81,43.33 90.81,42.7 90.49,42.38 89.85,42.38 89.53,42.7 89.53,43.33 89.85,43.65 90.17,43.65 | 82.55,39.84 82.87,39.84 83.19,39.52 83.19,38.89 82.87,38.57 82.23,38.57 81.92,38.89 81.92,39.52 82.23,39.84 82.55,39.84
VCC
  Bottom 0.406: 64.77,4.92 64.77,5.23 | 64.77,4.92 66.04,3.65 66.04,0.79 65.72,0.79 | 64.77,4.92 63.5,3.65 63.5,0.79 | 48.26,1.1 48.26,11.27 50.8,11.27 50.8,0.79
  Bottom 0.61: 8.89,47.46 9.21,47.46 9.53,47.14 9.53,46.51 9.21,46.19 8.57,46.19 8.26,46.51 8.26,47.14 8.57,47.46 8.89,47.46 | D1.P$1 8.89,47.46
  Bottom 1.016: IC3.14 69.85,20.16 67.94,18.25 67.94,11.9 64.77,8.73 27-VCC.1 64.77,5.23 | 65.72,0.79 50.8,0.79 20.95,0.79 20.95,23.96 | 20.95,23.96 IC2.14 | 48.26,11.27 48.26,13.81 | 48.26,13.81 IC5.10 48.26,19.52 40.96,19.52 40.96,32.86 C1.+ | 48.26,13.81 C2.1 | 21.59,35.4 20.95,35.4 20.95,23.96 | 21.59,35.4 R1.2 | 21.59,35.4 8.89,35.4 D1.P$1 6.35,46.83 6.35,63.34 17.14,63.34 17.14,57.62 20.95,57.62 20.95,63.34 41.91,63.34 IC1.14

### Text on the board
Bottom: CHEETAH | SPECDRUM | AMSTRAD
